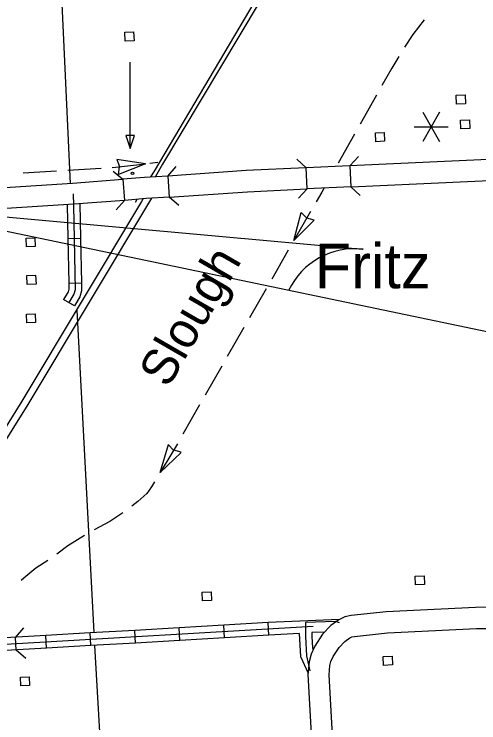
# Model space of a CAD drawing. Extents: x -0.3 to 2.65, y 0 to 1.9.
# Drawn here: x 0.7514 to 0.8173, y 0.2167 to 0.3171 of the extents above; entities that cross this region are included whole.
import ezdxf

# ---------------------------------------------------------------- set-up
doc = ezdxf.new("R2010")
doc.units = 0
for name, color, linetype in [('Default', 7, 'Continuous'), ('Level 12', 7, 'Continuous'), ('Level 14', 7, 'Continuous'), ('Level 15', 7, 'Continuous'), ('Level 16', 7, 'Continuous'), ('Level 19', 7, 'Continuous'), ('Level 20', 7, 'Continuous'), ('Level 21', 7, 'Continuous'), ('Level 24', 7, 'Continuous'), ('Level 29', 7, 'Continuous'), ('Level 30', 7, 'Continuous')]:
    doc.layers.add(name, color=color, linetype=linetype)

msp = doc.modelspace()

# ---------------------------------------------------------------- linework, layer by layer
at = {"layer": 'Default'}
msp.add_line((0.8008303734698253, 0.2838559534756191), (0.8008990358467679, 0.28382207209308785), dxfattribs=at)
msp.add_lwpolyline([(0.9717723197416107, 0.24008859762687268), (0.7329330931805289, 0.28998176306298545), (0.8008303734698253, 0.28385595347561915)], dxfattribs=at)
msp.add_arc((0.7996952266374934, 0.27354456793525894), 0.01034776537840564, 83.31935748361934, 154.5729957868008, dxfattribs=at)
at = {"layer": 'Level 12'}
for p, q in [((0.7659791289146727, 0.29653869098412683), (0.766381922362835, 0.29552295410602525)), ((0.7700421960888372, 0.29594093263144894), (0.7659791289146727, 0.29653869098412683)), ((0.7700421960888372, 0.29594093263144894), (0.7662246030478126, 0.29442706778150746)), ((0.7662246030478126, 0.29442706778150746), (0.7663837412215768, 0.2955087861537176)), ((0.791091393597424, 0.2850467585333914), (0.7921447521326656, 0.2890161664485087)), ((0.7921447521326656, 0.2890161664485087), (0.7929197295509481, 0.28824492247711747)), ((0.7939883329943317, 0.2879576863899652), (0.7929321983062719, 0.2882379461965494)), ((0.791091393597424, 0.2850467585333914), (0.7939883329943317, 0.2879576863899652)), ((0.7721464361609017, 0.252212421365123), (0.7733000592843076, 0.2561538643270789)), ((0.7732694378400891, 0.25614066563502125), (0.7740444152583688, 0.25536942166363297)), ((0.7721464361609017, 0.252212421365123), (0.7751162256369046, 0.255048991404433)), ((0.7751130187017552, 0.25508218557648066), (0.7740568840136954, 0.25536244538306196))]:
    msp.add_line(p, q, dxfattribs=at)
for points in [[(0.8095457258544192, 0.31630905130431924), (0.8079704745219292, 0.314241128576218), (0.8067736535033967, 0.31246824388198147)], [(0.8059535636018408, 0.311118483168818), (0.804969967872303, 0.30948361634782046), (0.8035765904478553, 0.30701964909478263)], [(0.8027990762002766, 0.3056447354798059), (0.8004665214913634, 0.3015199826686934)], [(0.7996890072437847, 0.3001450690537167), (0.7973564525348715, 0.29602031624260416)], [(0.759027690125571, 0.2950214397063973), (0.763756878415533, 0.2953201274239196)], [(0.7653332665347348, 0.2954196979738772), (0.7658260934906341, 0.2954508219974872), (0.7700424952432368, 0.2959409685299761)], [(0.7527221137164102, 0.2946231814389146), (0.7574513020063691, 0.29492186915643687)], [(0.7953159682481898, 0.2924120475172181), (0.7950433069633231, 0.29192989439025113), (0.7942372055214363, 0.2905258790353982)], [(0.7934507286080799, 0.2891560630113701), (0.7910913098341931, 0.28504661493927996)], [(0.7903048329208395, 0.28367679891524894), (0.7879454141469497, 0.27956735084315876)], [(0.7871589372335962, 0.2781975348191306), (0.7847995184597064, 0.2740880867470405)], [(0.7840130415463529, 0.27271827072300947), (0.7816536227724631, 0.2686088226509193)], [(0.7808671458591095, 0.2672390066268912), (0.7785077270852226, 0.263129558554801)], [(0.7777212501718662, 0.26175974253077), (0.7753618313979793, 0.2576502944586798)], [(0.7745753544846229, 0.25628047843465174), (0.7738052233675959, 0.2549391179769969), (0.772146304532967, 0.2522121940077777)], [(0.7713253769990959, 0.2508627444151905), (0.7708953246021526, 0.2501558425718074), (0.7702293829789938, 0.24920284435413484), (0.7689709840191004, 0.24810466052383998), (0.7681135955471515, 0.2474506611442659)], [(0.7668577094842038, 0.24649270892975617), (0.7668371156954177, 0.24647699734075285), (0.765009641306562, 0.24524663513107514), (0.7627888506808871, 0.2440776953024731)], [(0.7614325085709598, 0.24326930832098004), (0.7590613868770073, 0.2418120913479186), (0.7574919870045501, 0.24064549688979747)], [(0.7561985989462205, 0.23973977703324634), (0.754527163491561, 0.23862955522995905), (0.7528019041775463, 0.23724739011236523), (0.7524115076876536, 0.2369017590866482)]]:
    msp.add_lwpolyline(points, dxfattribs=at)
at = {"layer": 'Level 14'}
for points in [[(0.8092439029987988, 0.3576174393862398), (0.8091642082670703, 0.35781515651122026), (0.8087961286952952, 0.3577292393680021), (0.808624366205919, 0.35753286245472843), (0.808402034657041, 0.3572294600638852), (0.797550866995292, 0.33925935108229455), (0.7712708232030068, 0.29489538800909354)], [(0.8092439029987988, 0.3576174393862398), (0.7916393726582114, 0.3279704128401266), (0.7724750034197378, 0.2958663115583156), (0.7714869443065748, 0.29410766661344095)], [(0.7706519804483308, 0.29601182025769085), (0.7718031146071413, 0.296145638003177)], [(0.7706519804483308, 0.29601182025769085), (0.7718031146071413, 0.296145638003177)], [(0.7716114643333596, 0.2961233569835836), (0.7718031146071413, 0.296145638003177)], [(0.7712918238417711, 0.2948978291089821), (0.7707838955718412, 0.2940613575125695)], [(0.7695147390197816, 0.2905973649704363), (0.7525410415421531, 0.26230260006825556), (0.7311573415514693, 0.2279022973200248)], [(0.7708960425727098, 0.29103858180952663), (0.7533631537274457, 0.2618116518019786), (0.7322010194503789, 0.22796704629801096)], [(0.7688334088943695, 0.29084922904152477), (0.7685985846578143, 0.2904625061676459)], [(0.769683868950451, 0.2908983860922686), (0.7695147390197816, 0.2905973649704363)]]:
    msp.add_lwpolyline(points, dxfattribs=at)
at = {"layer": 'Level 15'}
for p, q in [((0.7590585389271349, 0.285345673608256), (0.7608531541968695, 0.28537871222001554)), ((0.7591748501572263, 0.27902859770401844), (0.7609694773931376, 0.27906164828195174)), ((0.759984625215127, 0.2758020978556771), (0.7584446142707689, 0.2767241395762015)), ((0.7875574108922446, 0.22913566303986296), (0.7874535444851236, 0.23092758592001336)), ((0.7749423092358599, 0.2284044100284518), (0.7748384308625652, 0.2301963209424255)), ((0.7812498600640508, 0.22877003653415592), (0.7811459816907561, 0.23056194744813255)), ((0.7560196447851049, 0.227307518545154), (0.7559157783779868, 0.22909942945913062)), ((0.7623271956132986, 0.22767314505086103), (0.7622233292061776, 0.22946506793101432)), ((0.7686347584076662, 0.22803877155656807), (0.7685308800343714, 0.22983069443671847)), ((0.7517138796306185, 0.2270385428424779), (0.7516341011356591, 0.22883169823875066))]:
    msp.add_line(p, q, dxfattribs=at)
for points in [[(0.7598122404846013, 0.2916787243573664), (0.7598535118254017, 0.29002036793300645)], [(0.7589705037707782, 0.29012683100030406), (0.7590585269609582, 0.285345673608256)], [(0.7607634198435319, 0.29025283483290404), (0.7608531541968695, 0.28537871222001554)], [(0.7598535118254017, 0.29002036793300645), (0.7600738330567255, 0.27805506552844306), (0.7599080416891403, 0.27744751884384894), (0.7592034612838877, 0.27627668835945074)], [(0.7590585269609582, 0.285345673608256), (0.7591748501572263, 0.27902859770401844)], [(0.7608531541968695, 0.28537871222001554), (0.7609694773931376, 0.279061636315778)], [(0.7591748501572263, 0.27902859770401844), (0.7591907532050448, 0.2781651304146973), (0.7590903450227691, 0.27779715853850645), (0.7584446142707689, 0.2767241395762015)], [(0.7609694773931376, 0.279061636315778), (0.7609901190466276, 0.2779408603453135), (0.7607564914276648, 0.2770847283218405), (0.759984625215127, 0.2758020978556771)], [(0.7874535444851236, 0.23092758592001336), (0.7811459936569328, 0.23056194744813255)], [(0.7975360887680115, 0.23138301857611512), (0.7874535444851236, 0.23092758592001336)], [(0.7975784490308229, 0.23088977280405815), (0.7969961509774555, 0.23106931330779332), (0.7927395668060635, 0.23093721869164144)], [(0.7927395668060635, 0.23093721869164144), (0.7927398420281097, 0.22895548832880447), (0.7928911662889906, 0.22623546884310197), (0.7933407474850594, 0.2241045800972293)], [(0.7938139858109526, 0.2303807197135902), (0.7502312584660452, 0.2278543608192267), (0.7281598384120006, 0.22687230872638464), (0.6998077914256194, 0.22549235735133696), (0.6698286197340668, 0.2249323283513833), (0.639886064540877, 0.22407358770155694), (0.6230656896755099, 0.22320564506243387), (0.6083784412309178, 0.22257210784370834), (0.5768441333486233, 0.22085329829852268), (0.5606983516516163, 0.2201700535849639), (0.5133923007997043, 0.2176997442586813), (0.5126551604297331, 0.21786072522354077), (0.5115988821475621, 0.21848861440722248), (0.510581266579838, 0.21876984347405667), (0.5086319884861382, 0.21899962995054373)], [(0.774838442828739, 0.2301963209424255), (0.7685308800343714, 0.22983069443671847)], [(0.7811459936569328, 0.23056194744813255), (0.774838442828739, 0.2301963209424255)], [(0.7559157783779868, 0.22909942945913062), (0.7501844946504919, 0.22876721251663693), (0.7496200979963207, 0.22874210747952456)], [(0.7622233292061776, 0.22946506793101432), (0.7559157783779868, 0.22909942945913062)], [(0.7685308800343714, 0.22983069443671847), (0.7622233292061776, 0.22946506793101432)], [(0.7875574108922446, 0.22913566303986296), (0.7812498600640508, 0.22877002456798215)], [(0.7918337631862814, 0.2293835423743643), (0.7875574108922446, 0.22913566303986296)], [(0.7918337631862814, 0.2293835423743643), (0.7920153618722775, 0.2261194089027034), (0.7930970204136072, 0.22377133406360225)], [(0.7954557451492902, 0.22959597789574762), (0.793653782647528, 0.22954005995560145)], [(0.793653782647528, 0.2295437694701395), (0.7936537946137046, 0.22948719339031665)], [(0.793653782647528, 0.22954005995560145), (0.7936538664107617, 0.22898095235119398), (0.7937127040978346, 0.2273376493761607), (0.7938139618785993, 0.22708437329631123)], [(0.7686347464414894, 0.22803877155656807), (0.7623271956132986, 0.22767314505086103)], [(0.7749423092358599, 0.2284043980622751), (0.7686347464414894, 0.22803877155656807)], [(0.7812498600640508, 0.22877002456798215), (0.7749423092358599, 0.2284043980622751)], [(0.7560196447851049, 0.22730750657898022), (0.7502763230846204, 0.22697459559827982), (0.749699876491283, 0.22694895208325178)], [(0.7623271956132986, 0.22767314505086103), (0.7560196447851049, 0.22730750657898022)]]:
    msp.add_lwpolyline(points, dxfattribs=at)
at = {"layer": 'Level 16'}
for p, q in [((0.8117526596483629, 0.3032284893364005), (0.8093594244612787, 0.2990832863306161)), ((0.8093594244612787, 0.3032284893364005), (0.8117526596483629, 0.2990832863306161)), ((0.8081628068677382, 0.3011558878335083), (0.8129492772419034, 0.3011558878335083))]:
    msp.add_line(p, q, dxfattribs=at)
at = {"layer": 'Level 19'}
for points in [[(0.767181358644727, 0.31330984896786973), (0.7671263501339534, 0.314554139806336), (0.7683743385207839, 0.3146093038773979), (0.7684293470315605, 0.3133650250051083)], [(0.8141637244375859, 0.3043852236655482), (0.8141087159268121, 0.3056295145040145), (0.8153567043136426, 0.30568467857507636), (0.8154117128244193, 0.3044403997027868)], [(0.8147784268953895, 0.30085871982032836), (0.8147234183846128, 0.30210301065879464), (0.8159714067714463, 0.3021581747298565), (0.8160264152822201, 0.300913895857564)], [(0.8027012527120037, 0.29905419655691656), (0.80264624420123, 0.3002984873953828), (0.8038942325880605, 0.3003536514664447), (0.8039492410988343, 0.2991093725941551)], [(0.7685037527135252, 0.29993917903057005), (0.7672832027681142, 0.29993917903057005), (0.7678934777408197, 0.2981083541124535)], [(0.7531904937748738, 0.28414120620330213), (0.7531378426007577, 0.285385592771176), (0.7543859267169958, 0.28543841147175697), (0.7544385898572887, 0.2841940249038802)], [(0.7532939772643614, 0.27883819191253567), (0.7532413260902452, 0.28008257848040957), (0.7544894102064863, 0.2801353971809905), (0.7545420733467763, 0.2788910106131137)], [(0.7532313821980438, 0.2733799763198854), (0.7531787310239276, 0.2746243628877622), (0.7544268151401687, 0.2746771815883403), (0.7544794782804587, 0.2734327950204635)], [(0.8083426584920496, 0.23627476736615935), (0.8082900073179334, 0.23751915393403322), (0.8095380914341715, 0.2375719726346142), (0.8095907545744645, 0.2363275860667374)], [(0.7781520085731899, 0.233997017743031), (0.7780993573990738, 0.2352414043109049), (0.7793474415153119, 0.23529422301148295), (0.7794001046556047, 0.23404983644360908)], [(0.8038113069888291, 0.22487983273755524), (0.803758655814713, 0.22612421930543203), (0.8050067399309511, 0.2261770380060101), (0.8050594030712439, 0.22493265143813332)], [(0.7523750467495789, 0.22196137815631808), (0.7523223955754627, 0.22320576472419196), (0.7535704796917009, 0.22325858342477), (0.7536231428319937, 0.22201419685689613)]]:
    msp.add_lwpolyline(points, close=True, dxfattribs=at)
msp.add_lwpolyline([(0.7678934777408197, 0.2981083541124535), (0.7678934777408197, 0.31033286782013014)], dxfattribs=at)
msp.add_circle((0.7682164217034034, 0.29456979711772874), 0.00017949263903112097, dxfattribs=at)
at = {"layer": 'Level 20'}
for points in [[(0.7565528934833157, 0.3542555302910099), (0.7593850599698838, 0.29315050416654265)], [(0.7603280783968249, 0.2751729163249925), (0.7627466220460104, 0.22951623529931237)], [(0.7628480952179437, 0.2276760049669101), (0.7653639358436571, 0.18359376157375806)]]:
    msp.add_lwpolyline(points, dxfattribs=at)
at = {"layer": 'Level 21'}
for points in [[(0.8207288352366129, 0.2966461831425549), (0.7990293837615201, 0.2956388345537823)], [(0.7928065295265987, 0.29534994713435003), (0.7843463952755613, 0.2949572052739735), (0.7732103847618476, 0.29419543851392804)], [(0.7990293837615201, 0.2956388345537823), (0.7928181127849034, 0.2953504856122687)], [(0.7929676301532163, 0.2923626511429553), (0.7928288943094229, 0.2953509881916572)], [(0.799042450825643, 0.2956394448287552), (0.7991811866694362, 0.29265110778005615)], [(0.7732103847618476, 0.29419543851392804), (0.7699277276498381, 0.2939708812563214), (0.7668587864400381, 0.2937306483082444)], [(0.7732231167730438, 0.2941963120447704), (0.7734272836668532, 0.2912117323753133)], [(0.707631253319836, 0.2903830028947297), (0.7105631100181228, 0.2904822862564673), (0.7280020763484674, 0.29116920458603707), (0.7597067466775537, 0.293170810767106), (0.7668587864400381, 0.2937306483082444)], [(0.7668528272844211, 0.29373018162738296), (0.7670862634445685, 0.29074775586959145)], [(0.7991931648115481, 0.2926516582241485), (0.8208573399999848, 0.29365736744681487)], [(0.773424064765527, 0.2912115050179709), (0.7845178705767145, 0.2919703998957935), (0.792933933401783, 0.2923610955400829)], [(0.7991926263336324, 0.2926516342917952), (0.792933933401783, 0.2923610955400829)], [(0.773424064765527, 0.2912115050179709), (0.7701465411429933, 0.29098730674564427), (0.7670822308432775, 0.29074744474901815)], [(0.7670816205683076, 0.29074739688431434), (0.7599177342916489, 0.2901866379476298), (0.7281552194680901, 0.28818137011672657), (0.7106726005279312, 0.28749272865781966), (0.7077114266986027, 0.2873924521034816)], [(0.8185009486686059, 0.23310757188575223), (0.8168505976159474, 0.23307155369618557), (0.804150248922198, 0.2324496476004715), (0.7992273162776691, 0.23194666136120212), (0.7983228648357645, 0.2317702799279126), (0.7974511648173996, 0.2313223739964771), (0.796312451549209, 0.23050915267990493), (0.795161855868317, 0.2292827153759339), (0.7940497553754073, 0.22759792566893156), (0.793522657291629, 0.22644995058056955), (0.7932377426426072, 0.2253989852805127), (0.7930805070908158, 0.22358029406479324), (0.7961520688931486, 0.16878299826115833)], [(0.7991394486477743, 0.16894113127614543), (0.7960792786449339, 0.22353494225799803), (0.7961951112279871, 0.22487460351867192), (0.7963449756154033, 0.2254274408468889), (0.7966727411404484, 0.22614125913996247), (0.797518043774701, 0.22742187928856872), (0.7982917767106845, 0.22824661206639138), (0.7990123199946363, 0.2287611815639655), (0.7993123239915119, 0.2289153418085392), (0.7996665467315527, 0.22898441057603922), (0.8043755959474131, 0.22946554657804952), (0.8169564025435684, 0.23008161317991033), (0.8188226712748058, 0.23012234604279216)]]:
    msp.add_lwpolyline(points, dxfattribs=at)
at = {"layer": 'Level 29'}
for points in [[(0.7516339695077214, 0.22883464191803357), (0.7528275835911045, 0.23017517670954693)], [(0.7530783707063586, 0.2258491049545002), (0.7517378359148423, 0.22704273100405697)]]:
    msp.add_lwpolyline(points, dxfattribs=at)
at = {"layer": 'Level 30'}
for points in [[(0.7915021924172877, 0.2965599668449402), (0.7928288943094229, 0.2953509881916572)], [(0.7990424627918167, 0.2956394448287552), (0.8002514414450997, 0.29696613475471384)], [(0.7732231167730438, 0.2941963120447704), (0.7744027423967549, 0.29554918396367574)], [(0.7654884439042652, 0.29489646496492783), (0.7668528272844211, 0.29373018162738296)], [(0.7929676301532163, 0.2923626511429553), (0.7917586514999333, 0.29103596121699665)], [(0.8005078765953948, 0.2914421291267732), (0.7991811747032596, 0.29265110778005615)], [(0.7747801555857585, 0.29003210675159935), (0.7734272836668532, 0.2912117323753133)], [(0.7670862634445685, 0.29074775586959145), (0.7659199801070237, 0.28938338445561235)]]:
    msp.add_lwpolyline(points, dxfattribs=at)

# ---------------------------------------------------------------- texts
at = {"layer": 'Level 12'}
msp.add_text('Slough', height=0.005054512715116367, rotation=59.98986111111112, dxfattribs=at).set_placement((0.7732530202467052, 0.26401249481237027))
at = {"layer": 'Level 24'}
msp.add_text('Fritz', height=0.0063181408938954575, dxfattribs=at).set_placement((0.7940576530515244, 0.27828702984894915))

doc.saveas('drawing.dxf')
